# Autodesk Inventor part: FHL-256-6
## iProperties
Author: Ron Crain
Shininess: 60.0
Length Units: 11272
Angle Units: 11286
Time Units: 11279
Mass Units: 11290
Length Display Precision: 5
Angle Display Precision: 2
Compacted: True
PropertySet Name: _Private Model Information
Created: 2002-07
Part Number: FHL-256-6
Material: Steel, High Strength Low Alloy
Description: STUD, SELF CLINCH,  2-56 UNC X 0.375 in
Vendor: PENN ENG & MFG
Document SubType Name: Modeling
Designer: Ron Crain
Control State: 0
Master: False
Checked Out: False
PropertySet Name: Design Tracking Control
Density: 7.84
Volumn: 0.12502123273002705
Area: 1.8185517691006778
PropertySet Name: Model Information
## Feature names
1. Head [Extrusion]
2. Shank [Extrusion]
3. Chamfer
